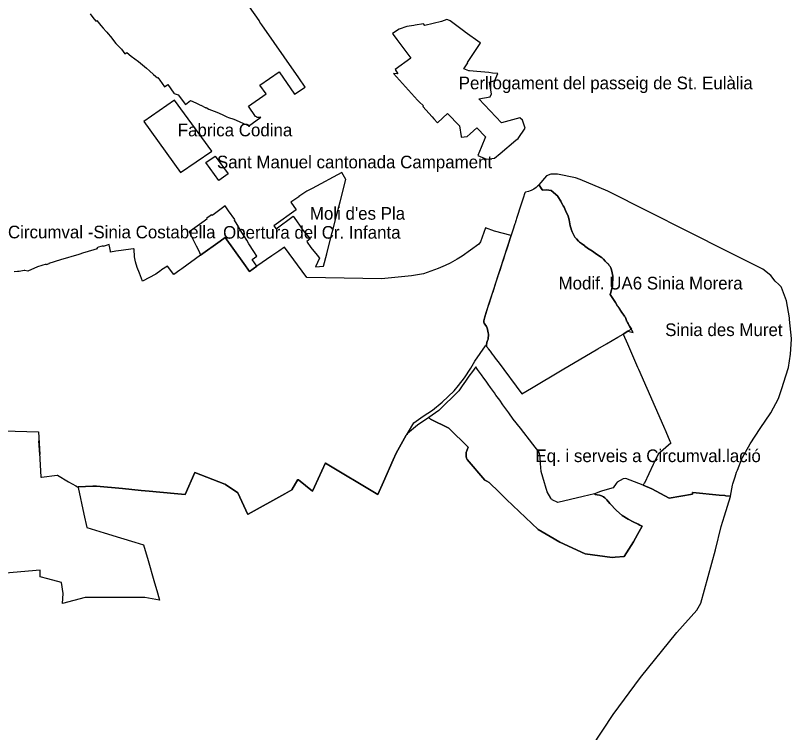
# Model space of a CAD drawing. Extents: x 599912 to 613490, y 4411003 to 4422920.
# Drawn here: x 608268 to 609004, y 4415128 to 4415809 of the extents above; entities that cross this region are included whole.
import ezdxf

# ---------------------------------------------------------------- set-up
doc = ezdxf.new("R2010")
doc.units = 0
for name, color, linetype in [('Pla Especial', 7, 'Continuous'), ('Pla Especial de Reforma Interior', 7, 'Continuous'), ('Sector amb disposicions transitòries', 7, 'Continuous'), ("Unitat d'Actuació", 7, 'Continuous'), ("Àrea d'interès Social", 7, 'Continuous')]:
    doc.layers.add(name, color=color, linetype=linetype)

msp = doc.modelspace()

# ---------------------------------------------------------------- linework, layer by layer
at = {"layer": 'Pla Especial'}
msp.add_lwpolyline([(608817.44, 4415354.93), (608806.51, 4415352.18), (608782.45, 4415346.78), (608777.27, 4415349.17), (608777.15, 4415349.37), (608776.62, 4415349.62), (608776.03, 4415350.66), (608772.48, 4415356.88), (608768.33, 4415370.68), (608766.88, 4415375.94), (608766.06, 4415383.72), (608765.71, 4415390.03), (608764.87, 4415394.54), (608764.61, 4415394.87), (608758.74, 4415401.99), (608747, 4415417.23), (608740.26, 4415425.76), (608736.01, 4415431.69), (608730.51, 4415439.39), (608727.37, 4415443.78), (608723.88, 4415448.66), (608722.47, 4415450.63), (608720.65, 4415453.18), (608718.67, 4415455.94), (608716.59, 4415458.85), (608714.46, 4415461.83), (608712.33, 4415464.82), (608710.24, 4415467.73), (608708.27, 4415470.49), (608706.45, 4415473.04), (608704.62, 4415475.6), (608701.45, 4415471.05), (608698.24, 4415466.45), (608695.02, 4415461.85), (608691.77, 4415457.27), (608688.57, 4415452.74), (608669.67, 4415434.06), (608660.04, 4415427.41), (608660.51, 4415426.84), (608661.01, 4415426.32), (608661.84, 4415425.9), (608679.1, 4415417.14), (608697.52, 4415399.3), (608695.59, 4415394.23), (608695.55, 4415393.86), (608695.41, 4415392.28), (608695.5, 4415390.42), (608695.93, 4415388.81), (608696.47, 4415387.6), (608713.16, 4415367.82), (608713.3, 4415367.81), (608714.41, 4415367.35), (608715.31, 4415366.98), (608717.31, 4415365.7), (608726.84, 4415356.33), (608733.87, 4415349.64), (608764.07, 4415321), (608775.36, 4415314.45), (608784.63, 4415309.08), (608808.71, 4415298.05), (608834.33, 4415294.39), (608836.99, 4415294.63), (608837.09, 4415294.68), (608845.67, 4415295.23), (608854.57, 4415309.35), (608858.29, 4415316.26), (608862.61, 4415324.25), (608860.6, 4415325.13), (608858.85, 4415326.05), (608854.11, 4415328.3), (608849.49, 4415330.66), (608843.83, 4415334.17), (608838.21, 4415339.02), (608832.13, 4415345.71), (608829.05, 4415349.3), (608827.37, 4415350.98), (608826.07, 4415351.94), (608824.21, 4415352.9), (608822.21, 4415353.59), (608819.86, 4415354.06), (608818.43, 4415354.12)], close=True, dxfattribs=at)
at = {"layer": 'Pla Especial de Reforma Interior'}
for points in [[(608717.86, 4415745.6), (608722.64, 4415747.39), (608725.65, 4415753.84), (608720.61, 4415754.38), (608717.03, 4415754.74), (608705.66, 4415755.9), (608698.83, 4415756.36), (608698.16, 4415756.41), (608693.21, 4415758.3), (608697.05, 4415764.14), (608696.67, 4415764.32), (608708.99, 4415782.48), (608709.17, 4415782.79), (608708.8, 4415783), (608694.71, 4415793.33), (608694.27, 4415793.65), (608680.4, 4415803.88), (608679.75, 4415804.29), (608677.32, 4415805.22), (608672.27, 4415803.41), (608656.35, 4415799.38), (608654.91, 4415800.95), (608647.23, 4415799.78), (608645.72, 4415799.56), (608639.11, 4415798.6), (608631.83, 4415795.99), (608625.52, 4415791.84), (608626.33, 4415790.89), (608629.62, 4415786.35), (608642.98, 4415768.41), (608628, 4415757.73), (608630.78, 4415753.57), (608626.58, 4415754), (608640.69, 4415738.21), (608649.27, 4415728.6), (608651.01, 4415727.1), (608654.91, 4415723.26), (608654.37, 4415722.75), (608663.13, 4415712.75), (608664.81, 4415710.82), (608668.39, 4415706.95), (608668.77, 4415707.29), (608677.98, 4415716), (608689.2, 4415704.13), (608690.75, 4415694.21), (608690.86, 4415693.5), (608696.49, 4415693.99), (608699.46, 4415696.74), (608705.62, 4415702.42), (608713.97, 4415693.93), (608709.68, 4415683.53), (608706.51, 4415676.17), (608714.87, 4415672.7), (608722.48, 4415673.61), (608727.77, 4415678.06), (608742.57, 4415690.54), (608744.86, 4415692.29), (608751.47, 4415701.99), (608748.94, 4415709.6), (608746.6, 4415711.72), (608729.18, 4415706.97), (608707.44, 4415729.9), (608718.42, 4415731.84), (608719.48, 4415734.7)], [(608575.75, 4415632.13), (608581.32, 4415653.27), (608577.64, 4415659.92), (608549.2, 4415644.87), (608544.2, 4415642.21), (608536.58, 4415637.15), (608536.73, 4415636.93), (608529.21, 4415631.66), (608534.08, 4415624.46), (608512.94, 4415609.43), (608515.13, 4415606.41), (608531.38, 4415618.37), (608534.49, 4415614.01), (608537.98, 4415608.99), (608540.56, 4415605.29), (608547.38, 4415596.82), (608544.15, 4415594.43), (608544.51, 4415593.94), (608548.15, 4415588.9), (608554.07, 4415581.33), (608556.26, 4415578.63), (608554.35, 4415574.53), (608552.35, 4415570.3), (608560.19, 4415570.91), (608563.3, 4415582.67), (608568.08, 4415601.98), (608569.18, 4415606.28), (608572.49, 4415619.19)]]:
    msp.add_lwpolyline(points, close=True, dxfattribs=at)
at = {"layer": 'Sector amb disposicions transitòries'}
for points in [[(608803.71, 4415653.22), (608799.29, 4415654.81), (608782.25, 4415658.52), (608776.04, 4415658.47), (608771.87, 4415656.69), (608764.57, 4415648.2), (608764.72, 4415647.97), (608767.96, 4415643.22), (608771.75, 4415643.56), (608776.32, 4415643), (608782.6, 4415637.39), (608782.68, 4415637.32), (608785.3, 4415632.76), (608785.46, 4415632.47), (608787.08, 4415629.65), (608787.82, 4415628.37), (608788.53, 4415627.06), (608789.98, 4415623.79), (608792.27, 4415618.61), (608793.29, 4415614.91), (608793.84, 4415611.34), (608794.37, 4415609.33), (608794.37, 4415609.32), (608795.14, 4415606.42), (608795.23, 4415606.14), (608795.24, 4415606.11), (608796.1, 4415603.5), (608798.81, 4415598.42), (608800.24, 4415596.93), (608802.3, 4415594.8), (608802.86, 4415594.22), (608803.23, 4415593.94), (608805.16, 4415592.5), (608808.08, 4415590.31), (608808.09, 4415590.31), (608808.24, 4415590.2), (608808.32, 4415590.14), (608810.47, 4415588.39), (608810.72, 4415588.18), (608813.78, 4415586.27), (608815.37, 4415585.2), (608819.39, 4415582.49), (608821.8, 4415580.86), (608824.14, 4415579.28), (608824.54, 4415578.94), (608825.94, 4415577.76), (608827.64, 4415575.92), (608828.52, 4415574.92), (608829.05, 4415574.32), (608829.09, 4415574.28), (608829.24, 4415574.16), (608829.83, 4415573.69), (608829.99, 4415573.56), (608830.63, 4415573.05), (608830.66, 4415573.03), (608831.47, 4415571.81), (608832.21, 4415570.7), (608832.6, 4415570.11), (608833.04, 4415569.46), (608833.25, 4415568.49), (608833.74, 4415566.33), (608834.83, 4415561.43), (608834.53, 4415551.9), (608832.51, 4415545.21), (608832.49, 4415545.16), (608832.15, 4415544.01), (608837.24, 4415536.41), (608839.41, 4415533.18), (608840.46, 4415531.61), (608843.5, 4415527.07), (608844.42, 4415525.71), (608845.27, 4415524.44), (608845.97, 4415523.39), (608846.37, 4415522.79), (608846.8, 4415522.16), (608847.75, 4415519.36), (608847.91, 4415518.87), (608847.93, 4415518.83), (608848.03, 4415518.68), (608848.69, 4415517.64), (608849.34, 4415516.54), (608849.51, 4415516.24), (608850.73, 4415514.18), (608852.49, 4415511.19), (608849.04, 4415509.16), (608849.04, 4415509.15), (608844.7, 4415506.61), (608848.64, 4415497.19), (608858.26, 4415475.25), (608859.15, 4415473.22), (608882.83, 4415419.24), (608885.06, 4415413.96), (608889.1, 4415404.94), (608889.98, 4415402.99), (608889.96, 4415402.98), (608877.72, 4415392.58), (608874.75, 4415385.93), (608873.23, 4415382.74), (608864.75, 4415364.9), (608864.68, 4415364.94), (608863.49, 4415363.01), (608871.73, 4415359.76), (608888.46, 4415350.75), (608910.56, 4415354.43), (608910.55, 4415355.93), (608910.55, 4415356.12), (608910.65, 4415356.11), (608935.65, 4415353.69), (608941.1, 4415353.16), (608942.21, 4415353.05), (608946.45, 4415352.79), (608948.52, 4415363.18), (608948.85, 4415364.26), (608950.94, 4415370.95), (608952.37, 4415375.55), (608953.09, 4415377.34), (608957.48, 4415388.2), (608958.04, 4415389.24), (608965.18, 4415402.31), (608974.74, 4415417.01), (608984.77, 4415431.82), (608992, 4415445.47), (608995.74, 4415455.73), (608997.01, 4415459.85), (609001.67, 4415474.91), (609003.54, 4415487.39), (609004.43, 4415501.6), (609004.47, 4415502.2), (609002.72, 4415520.51), (609002.48, 4415521.86), (608999.69, 4415538.05), (608995.14, 4415550.76), (608994.83, 4415551.32), (608992.34, 4415553.67), (608988.92, 4415556.92), (608984.84, 4415562.12), (608977.3, 4415568.31), (608944.46, 4415584.66), (608829.97, 4415642.11)], [(608767.79, 4415643.47), (608764.72, 4415647.98), (608764.72, 4415647.97), (608764.63, 4415647.89), (608764.37, 4415647.63), (608763.4, 4415646.82), (608762.18, 4415645.83), (608759.82, 4415644.26), (608757.31, 4415642.96), (608756.4, 4415642.59), (608754.68, 4415641.91), (608751.95, 4415641.15), (608751.64, 4415640.93), (608751.28, 4415640.51), (608749.75, 4415635.69), (608748.51, 4415631.75), (608746.95, 4415626.9), (608744.34, 4415619.15), (608743.71, 4415617.13), (608743.45, 4415616.28), (608743.06, 4415615.05), (608742.48, 4415613.23), (608742.24, 4415612.51), (608741.79, 4415611.13), (608739.79, 4415605.05), (608737.43, 4415597.75), (608734.7, 4415589.34), (608732.31, 4415581.97), (608730.89, 4415577.57), (608729.49, 4415573.25), (608727.72, 4415567.81), (608725.46, 4415560.83), (608723.85, 4415555.87), (608720.72, 4415546.28), (608720.34, 4415545.12), (608717.4, 4415536), (608715.96, 4415531.53), (608713.21, 4415523.03), (608712.25, 4415519.24), (608712.24, 4415518.65), (608712.3, 4415518.07), (608712.45, 4415517.5), (608712.67, 4415516.95), (608713.99, 4415514.94), (608714.16, 4415514.63), (608714.73, 4415513.61), (608715.36, 4415512.23), (608715.69, 4415511.32), (608715.87, 4415510.8), (608716.26, 4415509.33), (608716.53, 4415507.83), (608716.66, 4415506.31), (608716.67, 4415504.79), (608716.55, 4415503.27), (608716.31, 4415501.77), (608715.94, 4415500.29), (608715.33, 4415498.64), (608714.72, 4415496.45), (608714.73, 4415495.63), (608714.94, 4415494.93), (608714.96, 4415494.84), (608715.23, 4415494.36), (608716, 4415493.33), (608716.54, 4415492.61), (608718.23, 4415490.34), (608720.27, 4415487.6), (608720.92, 4415486.72), (608724.08, 4415482.49), (608725.85, 4415480.12), (608748.44, 4415449.83), (608757.46, 4415455.29), (608786.7, 4415472.6), (608820.69, 4415492.53), (608828.71, 4415497.24), (608839.48, 4415503.56), (608844.7, 4415506.61), (608849.04, 4415509.15), (608849.04, 4415509.16), (608854.27, 4415508.12), (608854.29, 4415508.17), (608852.97, 4415510.39), (608852.63, 4415510.97), (608850.73, 4415514.19), (608849.52, 4415516.25), (608849.34, 4415516.55), (608848.69, 4415517.65), (608848.03, 4415518.68), (608847.93, 4415518.84), (608847.92, 4415518.87), (608847.75, 4415519.36), (608846.8, 4415522.17), (608846.38, 4415522.8), (608845.97, 4415523.4), (608845.27, 4415524.45), (608844.42, 4415525.72), (608843.51, 4415527.08), (608840.46, 4415531.62), (608839.41, 4415533.19), (608837.25, 4415536.42), (608832.15, 4415544.02), (608832.5, 4415545.17), (608832.51, 4415545.21), (608834.53, 4415551.91), (608834.83, 4415561.44), (608833.74, 4415566.33), (608833.26, 4415568.5), (608833.04, 4415569.47), (608832.61, 4415570.11), (608832.22, 4415570.7), (608831.48, 4415571.81), (608830.66, 4415573.04), (608830.63, 4415573.06), (608830, 4415573.56), (608829.83, 4415573.7), (608829.25, 4415574.16), (608829.09, 4415574.29), (608829.06, 4415574.32), (608828.52, 4415574.93), (608827.64, 4415575.92), (608825.94, 4415577.77), (608824.55, 4415578.94), (608824.14, 4415579.29), (608821.8, 4415580.86), (608819.39, 4415582.49), (608815.37, 4415585.2), (608813.78, 4415586.28), (608810.72, 4415588.19), (608810.47, 4415588.39), (608808.32, 4415590.14), (608808.24, 4415590.2), (608808.09, 4415590.32), (608808.09, 4415590.32), (608805.16, 4415592.51), (608803.23, 4415593.95), (608802.86, 4415594.23), (608802.3, 4415594.8), (608800.25, 4415596.93), (608798.81, 4415598.43), (608796.1, 4415603.5), (608795.24, 4415606.12), (608795.23, 4415606.15), (608795.14, 4415606.42), (608794.37, 4415609.33), (608794.37, 4415609.33), (608793.84, 4415611.34), (608793.29, 4415614.91), (608792.27, 4415618.61), (608789.98, 4415623.8), (608788.53, 4415627.07), (608787.82, 4415628.37), (608787.08, 4415629.66), (608785.47, 4415632.47), (608785.3, 4415632.76), (608782.68, 4415637.32), (608782.61, 4415637.39), (608776.32, 4415643), (608771.75, 4415643.56), (608767.96, 4415643.22)]]:
    msp.add_lwpolyline(points, close=True, dxfattribs=at)
msp.add_lwpolyline([(608179.13, 4415416.97), (608289.59, 4415413.83), (608290.81, 4415392.16), (608289.83, 4415405.16), (608291.74, 4415370.7), (608292.42, 4415370.79), (608307.22, 4415372.57), (608307.42, 4415372.45), (608317.96, 4415366.35), (608324.91, 4415362.33), (608326.45, 4415361.43), (608327, 4415361.46), (608340.92, 4415362.07), (608344, 4415362.21), (608344.39, 4415362.17), (608369.36, 4415359.83), (608386.9, 4415358.18), (608394.43, 4415357.45), (608418.32, 4415355.15), (608428.69, 4415354.14), (608438.05, 4415375.08), (608466.48, 4415364.06), (608466.58, 4415363.99), (608466.8, 4415363.84), (608467.11, 4415363.62), (608478.68, 4415355.69), (608488.18, 4415335.23), (608488.35, 4415335.32), (608488.53, 4415335.42), (608523.39, 4415354.95), (608529.99, 4415358.66), (608535.64, 4415368.51), (608535.89, 4415368.31), (608535.95, 4415368.26), (608536.25, 4415368.02), (608549.62, 4415357.4), (608549.63, 4415357.44), (608549.64, 4415357.45), (608551.52, 4415361.57), (608561.86, 4415384.2), (608562.13, 4415384.04), (608611.6, 4415354.26), (608611.62, 4415354.28), (608616.95, 4415366.4), (608626.14, 4415387.26), (608628.93, 4415393.59), (608638.53, 4415410.51), (608639.3, 4415411.21), (608639.83, 4415412.11), (608645.91, 4415422.29), (608654.83, 4415428.56), (608663.59, 4415434.4), (608672.76, 4415441.85), (608684.02, 4415452.73), (608688.24, 4415457.59), (608693.9, 4415464.95), (608700.03, 4415474.26), (608703.8, 4415480.97), (608714.06, 4415495.25), (608714.72, 4415496.45), (608715.33, 4415498.64), (608715.94, 4415500.29), (608716.31, 4415501.77), (608716.55, 4415503.27), (608716.67, 4415504.79), (608716.66, 4415506.31), (608716.53, 4415507.83), (608716.26, 4415509.33), (608715.87, 4415510.8), (608715.68, 4415511.31), (608715.36, 4415512.23), (608714.73, 4415513.61), (608713.99, 4415514.94), (608712.67, 4415516.95), (608712.45, 4415517.5), (608712.3, 4415518.07), (608712.24, 4415518.65), (608712.25, 4415519.24), (608713.21, 4415523.03), (608717.4, 4415536), (608720.72, 4415546.28), (608738.17, 4415600.23), (608722.42, 4415604.29), (608713.83, 4415607.27), (608709.22, 4415594.13), (608707.54, 4415591.77), (608691.67, 4415580.6), (608686.95, 4415577.77), (608680.47, 4415573.94), (608675.51, 4415571.61), (608669.04, 4415568.68), (608655.02, 4415563.83), (608643.7, 4415561.83), (608615.2, 4415559.11), (608544.25, 4415560.39), (608523.19, 4415588.96), (608517.56, 4415585.4), (608510.86, 4415580.7), (608496.86, 4415570.9), (608489.73, 4415565.96), (608484.44, 4415573.61), (608466.62, 4415598.15), (608461.9, 4415594.87), (608443.27, 4415581.47), (608443.27, 4415581.47), (608425.4, 4415568.53), (608423.72, 4415567.32), (608423.64, 4415567.27), (608418.05, 4415563.25), (608412.04, 4415571.14), (608406.17, 4415567.44), (608405.54, 4415566.96), (608400.79, 4415563.43), (608388.29, 4415556.68), (608388.26, 4415556.77), (608388.25, 4415556.77), (608387.36, 4415559.18), (608385.21, 4415564.51), (608383.25, 4415569.6), (608381.61, 4415575.02), (608380.68, 4415579.94), (608380.15, 4415587.11), (608379.6, 4415587.78), (608379.25, 4415587.63), (608367.83, 4415585.86), (608367.83, 4415585.96), (608362.89, 4415585.22), (608357.91, 4415584.46), (608357.75, 4415585.23), (608356.89, 4415590.12), (608356.41, 4415591.41), (608356.4, 4415591.45), (608356.39, 4415591.46), (608350.95, 4415589.82), (608350.83, 4415590.21), (608346.49, 4415588.94), (608344.94, 4415588.43), (608345.24, 4415587.46), (608333.38, 4415583.95), (608332.1, 4415583.54), (608327.72, 4415582.12), (608310.37, 4415576.9), (608299.14, 4415573.62), (608299.17, 4415573.54), (608299.25, 4415573.27), (608299.2, 4415573.26), (608299.22, 4415573.21), (608296.77, 4415572.42), (608296.64, 4415572.8), (608288.54, 4415570.38), (608279.42, 4415566.4), (608276.31, 4415566.88), (608275.86, 4415566.81), (608271.22, 4415566.06), (608269.52, 4415566.02), (608266.34, 4415565.75)], dxfattribs=at)
at = {"layer": "Unitat d'Actuació"}
msp.add_lwpolyline([(608338.48, 4415810.58), (608341.06, 4415807.12), (608343.76, 4415803.5), (608344.87, 4415804.26), (608348.67, 4415799.53), (608350.75, 4415797), (608353.79, 4415793.79), (608354.25, 4415793.25), (608355.74, 4415791.49), (608357.83, 4415789.04), (608362.76, 4415782.28), (608368.22, 4415777.06), (608371.48, 4415772.77), (608373.21, 4415773.88), (608377.5, 4415770.45), (608384.26, 4415765.45), (608388.28, 4415762.16), (608392.02, 4415759.16), (608394.83, 4415756.52), (608394.73, 4415756.4), (608398.67, 4415753.07), (608402.42, 4415749.94), (608402.82, 4415750.21), (608404.53, 4415747.72), (608409.11, 4415741.26), (608412.29, 4415743.6), (608418, 4415735.36), (608418.23, 4415734.96), (608422.08, 4415733.58), (608428.94, 4415724.58), (608433.78, 4415728.19), (608438.74, 4415726.05), (608442.71, 4415724.15), (608443.32, 4415723.58), (608443.53, 4415723.75), (608448.44, 4415721.4), (608448.71, 4415721.62), (608451.28, 4415720.22), (608453.64, 4415719.19), (608458.71, 4415717.16), (608463.72, 4415714.86), (608468.21, 4415712.8), (608469.8, 4415712.3), (608474.83, 4415710.64), (608479.98, 4415708.34), (608484.02, 4415706.57), (608487.37, 4415705.05), (608488.4, 4415704.59), (608488.84, 4415704.06), (608500.54, 4415712.37), (608499.04, 4415712.06), (608498.4, 4415712.07), (608497.22, 4415712.29), (608496.33, 4415712.67), (608495.62, 4415713.11), (608488.82, 4415723.07), (608505.51, 4415734.65), (608499.47, 4415742.88), (608518, 4415755.58), (608532.61, 4415734.23), (608542.52, 4415741.03), (608536.5, 4415749.8), (608522.76, 4415769.74), (608513.08, 4415783.51), (608501.52, 4415800.19), (608499.77, 4415802.77), (608498.83, 4415804.15), (608489.93, 4415817.25)], dxfattribs=at)
for points in [[(608389.41, 4415708.38), (608424.21, 4415659.81), (608453.88, 4415680.12), (608418.58, 4415728.76)], [(608448.22, 4415669.36), (608457.19, 4415675.58), (608469.6, 4415658.8), (608460.74, 4415652.25), (608460.74, 4415652.25)], [(608478.23, 4415610.68), (608475.45, 4415614.58), (608475.8, 4415615.21), (608469.97, 4415623.46), (608466.8, 4415628.28), (608456.42, 4415620.76), (608454.2, 4415619.14), (608453.75, 4415619.75), (608448.83, 4415616.27), (608449.27, 4415615.64), (608446.67, 4415613.76), (608446.68, 4415613.75), (608435.82, 4415605.81), (608435.7, 4415605.97), (608432.54, 4415603.68), (608439.3, 4415590.17), (608440.96, 4415586.82), (608440.98, 4415586.78), (608442.19, 4415584.13), (608443.16, 4415581.74), (608443.27, 4415581.47), (608461.9, 4415594.87), (608466.62, 4415598.15), (608484.44, 4415573.61), (608489.73, 4415565.96), (608496.86, 4415570.9), (608492.39, 4415577.27), (608496.74, 4415580.39), (608493.94, 4415584.81), (608489.25, 4415592.2), (608487.13, 4415595.68), (608484.42, 4415600.11), (608482.66, 4415602.97)]]:
    msp.add_lwpolyline(points, close=True, dxfattribs=at)
at = {"layer": "Àrea d'interès Social"}
msp.add_lwpolyline([(608814.74, 4415114.67), (608835.03, 4415145.23), (608861.25, 4415180.52), (608895.74, 4415223.14), (608914.72, 4415244.55), (608918.34, 4415250.96), (608932.43, 4415301.54), (608937.57, 4415323.7), (608940.86, 4415334.07), (608946.68, 4415352.36), (608946.45, 4415352.79), (608942.21, 4415353.05), (608941.1, 4415353.16), (608935.65, 4415353.69), (608910.65, 4415356.11), (608910.55, 4415356.12), (608910.55, 4415355.93), (608910.56, 4415354.43), (608888.46, 4415350.75), (608871.73, 4415359.76), (608863.49, 4415363.01), (608847.32, 4415369.48), (608844.57, 4415369), (608838.86, 4415365.99), (608838.08, 4415364.53), (608835.15, 4415360.7), (608824.99, 4415357.86), (608823.07, 4415356.96), (608817.44, 4415354.93), (608818.43, 4415354.12), (608819.86, 4415354.06), (608822.21, 4415353.59), (608824.21, 4415352.9), (608826.07, 4415351.94), (608827.37, 4415350.98), (608829.05, 4415349.3), (608832.13, 4415345.71), (608838.21, 4415339.02), (608843.83, 4415334.17), (608849.49, 4415330.66), (608854.11, 4415328.3), (608858.85, 4415326.05), (608860.6, 4415325.13), (608862.61, 4415324.25), (608858.29, 4415316.26), (608854.57, 4415309.35), (608845.67, 4415295.23), (608837.09, 4415294.68), (608836.99, 4415294.63), (608834.33, 4415294.39), (608808.71, 4415298.05), (608784.63, 4415309.08), (608775.36, 4415314.45), (608764.07, 4415321), (608733.87, 4415349.64), (608726.84, 4415356.33), (608717.31, 4415365.7), (608715.31, 4415366.98), (608714.41, 4415367.35), (608713.3, 4415367.81), (608713.16, 4415367.82), (608696.47, 4415387.6), (608695.93, 4415388.81), (608695.5, 4415390.42), (608695.41, 4415392.28), (608695.55, 4415393.86), (608695.59, 4415394.23), (608697.52, 4415399.3), (608679.1, 4415417.14), (608661.84, 4415425.9), (608661.01, 4415426.32), (608660.51, 4415426.84), (608660.04, 4415427.41), (608659.67, 4415427.15), (608655.22, 4415424.07), (608649.28, 4415419.96), (608639.83, 4415412.11), (608639.3, 4415411.21), (608638.53, 4415410.51), (608628.93, 4415393.59), (608626.14, 4415387.26), (608616.95, 4415366.4), (608611.62, 4415354.28), (608611.6, 4415354.26), (608562.13, 4415384.04), (608561.86, 4415384.2), (608551.52, 4415361.57), (608549.64, 4415357.45), (608549.63, 4415357.44), (608549.62, 4415357.4), (608536.25, 4415368.02), (608535.95, 4415368.26), (608535.89, 4415368.31), (608535.64, 4415368.51), (608529.99, 4415358.66), (608523.39, 4415354.95), (608488.53, 4415335.42), (608488.35, 4415335.32), (608488.18, 4415335.23), (608478.68, 4415355.69), (608467.11, 4415363.62), (608466.8, 4415363.84), (608466.58, 4415363.99), (608466.48, 4415364.06), (608438.05, 4415375.08), (608428.69, 4415354.14), (608418.32, 4415355.15), (608394.43, 4415357.45), (608386.9, 4415358.18), (608369.36, 4415359.83), (608344.39, 4415362.17), (608344, 4415362.21), (608340.92, 4415362.07), (608327, 4415361.46), (608327.09, 4415361), (608332.57, 4415335.51), (608335.35, 4415323.01), (608351.72, 4415317.99), (608367.28, 4415313.23), (608380.88, 4415309), (608389.2, 4415306.48), (608393.55, 4415291.57), (608399.1, 4415272.57), (608402.54, 4415261), (608404.21, 4415253.78), (608390.27, 4415256.38), (608333.64, 4415256.38), (608312.12, 4415250.72), (608312.87, 4415260.38), (608311.18, 4415270.66), (608298.44, 4415274.07), (608298.41, 4415274.08), (608290.87, 4415276.1), (608290.91, 4415282.38), (608243.37, 4415278.2)], dxfattribs=at)

# ---------------------------------------------------------------- texts
at = {"layer": 'Pla Especial'}
msp.add_text('Eq. i serveis a Circumval.lació', height=12, dxfattribs=at).set_placement((608761.33, 4415384.99))
at = {"layer": 'Pla Especial de Reforma Interior'}
for s, p in [('Perllogament del passeig de St. Eulàlia', (608688.49, 4415738.96)), ("Moli d'es Pla", (608547.13, 4415615.11))]:
    msp.add_text(s, height=12, dxfattribs=at).set_placement(p)
at = {"layer": 'Sector amb disposicions transitòries'}
for s, p in [('Psg Circumval -Sinia Costabella', (608228.32, 4415597.44)), ('Modif. UA6 Sinia Morera', (608783.27, 4415548.9)), ('Sinia des Muret', (608884.52, 4415504.64))]:
    msp.add_text(s, height=12, dxfattribs=at).set_placement(p)
at = {"layer": "Unitat d'Actuació"}
for s, p in [('Fabrica Codina', (608421.65, 4415694.29)), ('Sant Manuel cantonada Campament', (608458.91, 4415663.91)), ('Obertura del Cr. Infanta', (608464.7, 4415597.12))]:
    msp.add_text(s, height=12, dxfattribs=at).set_placement(p)

doc.saveas('drawing.dxf')
